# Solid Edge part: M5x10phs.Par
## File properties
Title: Pan Head Screw M5 x 10
Subject: Solid Edge Training
Author: ptcarter
Keywords: Pan Head Screw
Comments: Pan Head Screw M5 x 10
Template: normal.par
Last saved by: ptcarter
Revision: 24
Application: Solid Edge
Material: Steel
Category: Standard Parts
Manager: Tony Logan
Company: Intergraph Mechanical
Supplier: MidState Fasteners
Accuracy: 0.99
Document Number: phs510
Revision: 1
Project Name: Standard Parts
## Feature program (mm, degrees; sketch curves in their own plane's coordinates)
sketch for "unnamed RevolvedProtrusion 1" plane through (0, 0, 0) normal (0, -1, 0) x-axis (1, 0, 0)
  line (-10, 0) -> (-10, 2.5)
  line (-10, 2.5) -> (0, 2.5)
  line (0, 2.5) -> (0, 5)
  line (0, 5) -> (1, 5)
  arc centre (-7.6603, 0) radius 10 from (1, 5) to (2.3397, 0) cw
revolve "unnamed RevolvedProtrusion 1" add finite 360 deg about sketch line (-10, 0) -> (2.3397, 0)
sketch for "unnamed Cutout 1" plane through (3.175, 0, 0) normal (-1, 0, 0) x-axis (0, 1, 0)
  line (2.125, -0.375) -> (2.125, 0.375)
  line (2.125, 0.375) -> (0.375, 0.375)
  line (0.375, 0.375) -> (0.375, 2.125)
  line (0.375, 2.125) -> (-0.375, 2.125)
  line (-0.375, 2.125) -> (-0.375, 0.375)
  line (-0.375, 0.375) -> (-2.125, 0.375)
  line (-2.125, 0.375) -> (-2.125, -0.375)
  line (-2.125, -0.375) -> (-0.375, -0.375)
  line (-0.375, -0.375) -> (-0.375, -2.125)
  line (-0.375, -2.125) -> (0.375, -2.125)
  line (0.375, -2.125) -> (0.375, -0.375)
  line (0.375, -0.375) -> (2.125, -0.375)
extrude "unnamed Cutout 1" cut finite 3.175 along +normal
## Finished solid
Body 1: solid body, 18 faces, 40 edges, 24 vertices.
  Faces by surface: plane 15, cylinder 2, sphere 1
  Edges by curve: line 24, circle 16
Bounding box of the edges (mm; curved faces can reach further): 12.326 x 10.000 x 10.000, from (-10, -5, -5) to (2.3257, 5, 5).
Cylindrical faces by radius (mm): R2.5 x1, R5 x1
Spherical faces by radius (mm): R10 x1
Planar faces by outward normal: +x 1, +y 3, +z 3, -x 2, -y 3, -z 3
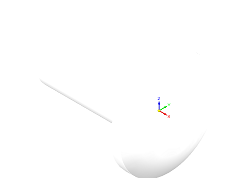
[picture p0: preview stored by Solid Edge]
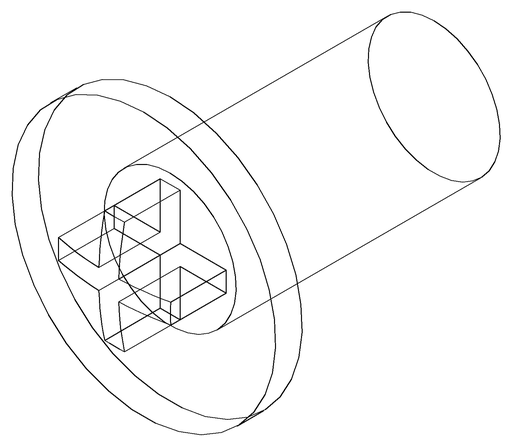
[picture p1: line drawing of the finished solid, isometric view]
